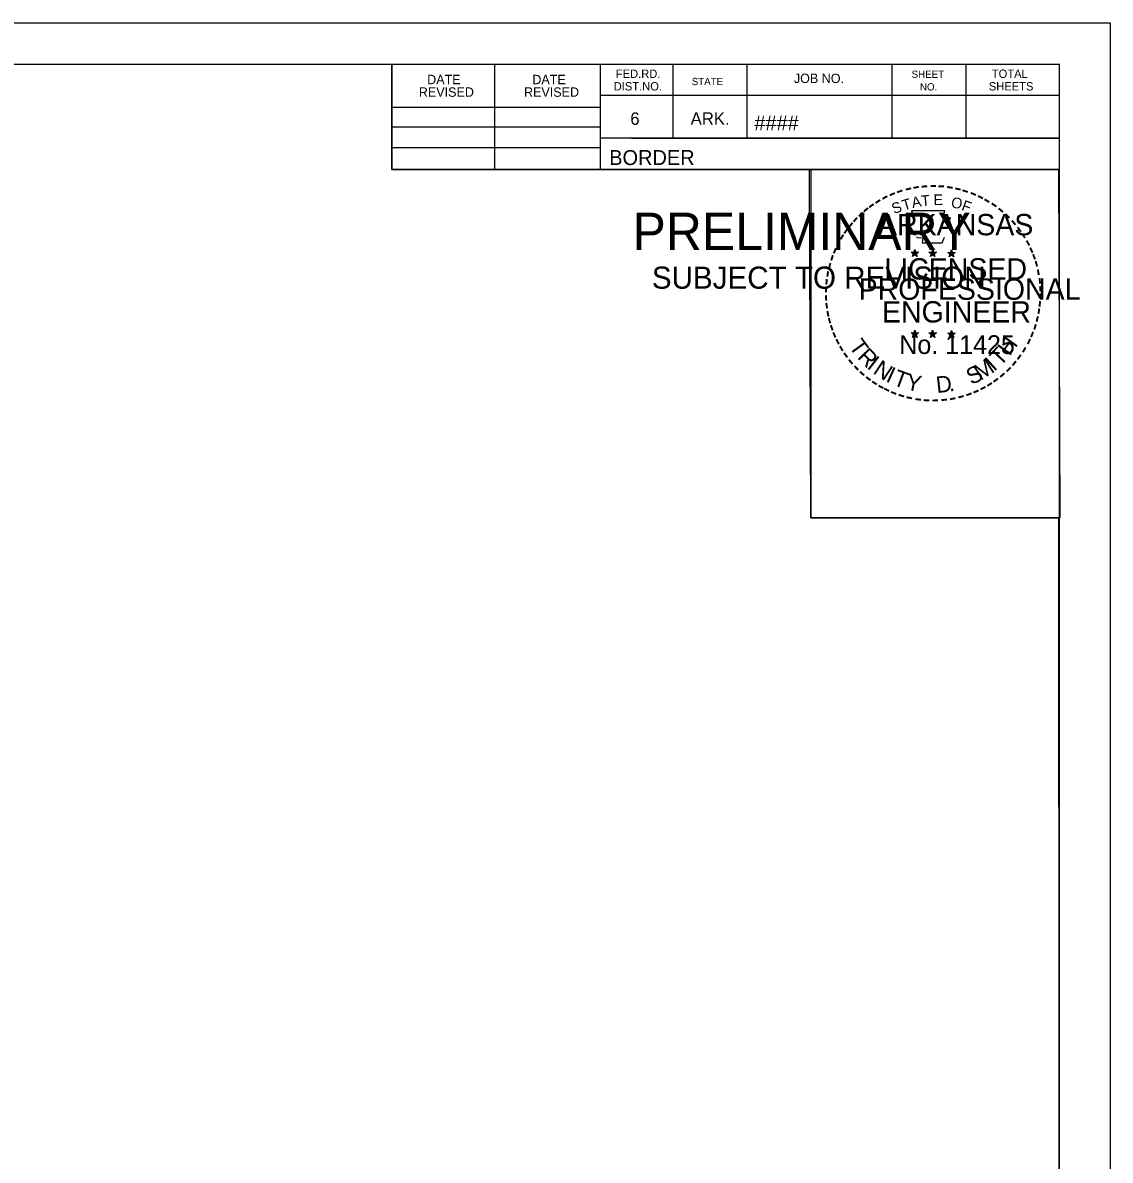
# Model space of a CAD drawing. Extents: x 961436 to 1372525, y 380079 to 2027791.
# Drawn here: x 1372422.8 to 1372524.7, y 380786.1 to 380892.8 of the extents above; entities that cross this region are included whole.
import ezdxf

# ---------------------------------------------------------------- set-up
doc = ezdxf.new("R2010")
doc.units = 0
for name, color, linetype in [('R_Border', 7, 'Continuous'), ('R_Border PE', 7, 'Continuous'), ('R_Border Prem', 7, 'Continuous'), ('R_No Plot', 7, 'Continuous')]:
    doc.layers.add(name, color=color, linetype=linetype)

msp = doc.modelspace()

# ---------------------------------------------------------------- linework, layer by layer
at = {"layer": 'R_Border'}
for p, q in [((1372203.81, 380888.88), (1372519.99, 380888.88)), ((1372457.35, 380879), (1372457.35, 380888.88)), ((1372467.03, 380879), (1372467.03, 380888.88)), ((1372476.89, 380888.88), (1372476.89, 380879)), ((1372483.73, 380888.88), (1372483.73, 380881.94)), ((1372490.67, 380888.88), (1372490.67, 380881.94)), ((1372504.25, 380888.88), (1372504.25, 380881.94)), ((1372511.19, 380888.88), (1372511.19, 380881.94)), ((1372519.99, 380683.42), (1372519.99, 380888.88)), ((1372519.99, 380885.94), (1372476.89, 380885.94)), ((1372519.99, 380885.96), (1372519.99, 380885.96)), ((1372457.35, 380884.86), (1372476.89, 380884.86)), ((1372457.35, 380883), (1372476.89, 380883)), ((1372519.99, 380881.94), (1372476.89, 380881.94)), ((1372479.85, 380881.94), (1372519.99, 380881.94)), ((1372457.35, 380881.06), (1372476.89, 380881.06)), ((1372519.99, 380879), (1372457.35, 380879))]:
    msp.add_line(p, q, dxfattribs=at)
at = {"layer": 'R_Border PE'}
for p, q in [((1372506.07, 380871.25), (1372506.42, 380871.14)), ((1372506.07, 380871.25), (1372506.32, 380871.21)), ((1372506.07, 380871.25), (1372506.31, 380871.13)), ((1372506.2, 380870.84), (1372506.42, 380871.14)), ((1372506.2, 380870.84), (1372506.33, 380871.09)), ((1372506.2, 380870.84), (1372506.42, 380871.06)), ((1372506.42, 380871.51), (1372506.38, 380871.25)), ((1372506.42, 380871.14), (1372506.42, 380871.51)), ((1372506.42, 380871.51), (1372506.47, 380871.26)), ((1372506.77, 380871.25), (1372506.42, 380871.14)), ((1372506.63, 380870.84), (1372506.42, 380871.14)), ((1372506.63, 380870.84), (1372506.42, 380871.06)), ((1372506.77, 380871.25), (1372506.48, 380871.2)), ((1372506.63, 380870.84), (1372506.5, 380871.13)), ((1372506.77, 380871.25), (1372506.56, 380871.15)), ((1372507.74, 380871.25), (1372508.09, 380871.14)), ((1372507.74, 380871.25), (1372507.99, 380871.21)), ((1372507.74, 380871.25), (1372507.98, 380871.13)), ((1372507.87, 380870.84), (1372508.09, 380871.14)), ((1372507.87, 380870.84), (1372508, 380871.09)), ((1372507.87, 380870.84), (1372508.09, 380871.06)), ((1372508.09, 380871.51), (1372508.05, 380871.25)), ((1372508.09, 380871.14), (1372508.09, 380871.51)), ((1372508.09, 380871.51), (1372508.14, 380871.26)), ((1372508.44, 380871.25), (1372508.09, 380871.14)), ((1372508.3, 380870.84), (1372508.09, 380871.14)), ((1372508.3, 380870.84), (1372508.09, 380871.06)), ((1372508.44, 380871.25), (1372508.15, 380871.2)), ((1372508.3, 380870.84), (1372508.17, 380871.13)), ((1372508.44, 380871.25), (1372508.23, 380871.15)), ((1372509.5, 380871.24), (1372509.85, 380871.13)), ((1372509.5, 380871.24), (1372509.76, 380871.19)), ((1372509.5, 380871.24), (1372509.74, 380871.12)), ((1372509.64, 380870.83), (1372509.85, 380871.13)), ((1372509.64, 380870.83), (1372509.76, 380871.08)), ((1372509.64, 380870.83), (1372509.85, 380871.05)), ((1372509.85, 380871.49), (1372509.81, 380871.24)), ((1372509.85, 380871.13), (1372509.85, 380871.49)), ((1372509.85, 380871.49), (1372509.9, 380871.24)), ((1372510.2, 380871.24), (1372509.85, 380871.13)), ((1372510.07, 380870.83), (1372509.85, 380871.13)), ((1372510.07, 380870.83), (1372509.85, 380871.05)), ((1372510.2, 380871.24), (1372509.91, 380871.19)), ((1372510.07, 380870.83), (1372509.93, 380871.12)), ((1372510.2, 380871.24), (1372510, 380871.14)), ((1372506.07, 380863.68), (1372506.42, 380863.57)), ((1372506.07, 380863.68), (1372506.32, 380863.63)), ((1372506.07, 380863.68), (1372506.3, 380863.56)), ((1372506.2, 380863.27), (1372506.42, 380863.57)), ((1372506.2, 380863.27), (1372506.33, 380863.51)), ((1372506.2, 380863.27), (1372506.41, 380863.49)), ((1372506.42, 380863.93), (1372506.37, 380863.68)), ((1372506.63, 380863.27), (1372506.41, 380863.48)), ((1372506.42, 380863.57), (1372506.42, 380863.93)), ((1372506.42, 380863.93), (1372506.46, 380863.68)), ((1372506.76, 380863.68), (1372506.42, 380863.57)), ((1372506.63, 380863.27), (1372506.42, 380863.57)), ((1372506.76, 380863.68), (1372506.48, 380863.63)), ((1372506.63, 380863.27), (1372506.49, 380863.56)), ((1372506.76, 380863.68), (1372506.56, 380863.58)), ((1372507.74, 380863.68), (1372508.08, 380863.57)), ((1372507.74, 380863.68), (1372507.99, 380863.63)), ((1372507.74, 380863.68), (1372507.97, 380863.56)), ((1372507.87, 380863.27), (1372508.08, 380863.57)), ((1372507.87, 380863.27), (1372507.99, 380863.51)), ((1372507.87, 380863.27), (1372508.08, 380863.49)), ((1372508.08, 380863.93), (1372508.04, 380863.68)), ((1372508.08, 380863.57), (1372508.08, 380863.93)), ((1372508.08, 380863.93), (1372508.13, 380863.68)), ((1372508.43, 380863.68), (1372508.08, 380863.57)), ((1372508.3, 380863.27), (1372508.08, 380863.57)), ((1372508.3, 380863.27), (1372508.08, 380863.48)), ((1372508.43, 380863.68), (1372508.15, 380863.63)), ((1372508.3, 380863.27), (1372508.16, 380863.56)), ((1372508.43, 380863.68), (1372508.23, 380863.58)), ((1372509.5, 380863.67), (1372509.85, 380863.56)), ((1372509.5, 380863.67), (1372509.76, 380863.62)), ((1372509.5, 380863.67), (1372509.74, 380863.55)), ((1372509.64, 380863.26), (1372509.85, 380863.56)), ((1372509.64, 380863.26), (1372509.76, 380863.5)), ((1372509.64, 380863.26), (1372509.85, 380863.48)), ((1372509.85, 380863.92), (1372509.81, 380863.67)), ((1372509.85, 380863.56), (1372509.85, 380863.92)), ((1372509.85, 380863.92), (1372509.9, 380863.67)), ((1372510.2, 380863.67), (1372509.85, 380863.56)), ((1372510.06, 380863.26), (1372509.85, 380863.56)), ((1372510.06, 380863.26), (1372509.85, 380863.47)), ((1372510.2, 380863.67), (1372509.91, 380863.62)), ((1372510.06, 380863.26), (1372509.93, 380863.55)), ((1372510.2, 380863.67), (1372509.99, 380863.57))]:
    msp.add_line(p, q, dxfattribs=at)
for points in [[(1372506.11, 380875.13), (1372506.38, 380874.3)], [(1372509.62, 380874.21), (1372509.76, 380874.49), (1372509.08, 380874.47), (1372509.23, 380875.13), (1372506.11, 380875.13)], [(1372506.6, 380872.71), (1372506.6, 380872.62), (1372507.17, 380872.6), (1372507.11, 380872.13), (1372508.98, 380872.13), (1372509.18, 380872.66)], [(1372506.42, 380871.51), (1372506.63, 380870.84), (1372506.07, 380871.25), (1372506.77, 380871.25), (1372506.2, 380870.84), (1372506.42, 380871.51)], [(1372508.09, 380871.51), (1372508.3, 380870.84), (1372507.74, 380871.25), (1372508.44, 380871.25), (1372507.87, 380870.84), (1372508.09, 380871.51)], [(1372509.85, 380871.49), (1372510.07, 380870.83), (1372509.5, 380871.24), (1372510.2, 380871.24), (1372509.64, 380870.83), (1372509.85, 380871.49)], [(1372506.42, 380863.93), (1372506.63, 380863.27), (1372506.07, 380863.68), (1372506.76, 380863.68), (1372506.2, 380863.27), (1372506.42, 380863.93)], [(1372508.08, 380863.93), (1372508.3, 380863.27), (1372507.74, 380863.68), (1372508.43, 380863.68), (1372507.87, 380863.27), (1372508.08, 380863.93)], [(1372509.85, 380863.92), (1372510.06, 380863.26), (1372509.5, 380863.67), (1372510.2, 380863.67), (1372509.64, 380863.26), (1372509.85, 380863.92)]]:
    msp.add_lwpolyline(points, dxfattribs=at)
for centre, radius in [((1372506.42, 380871.14), 0.172), ((1372506.42, 380871.14), 0.145), ((1372506.42, 380871.14), 0.116), ((1372506.42, 380871.14), 0.0991), ((1372506.42, 380871.14), 0.0747), ((1372506.42, 380871.14), 0.0495), ((1372506.42, 380871.14), 0.0296), ((1372508.09, 380871.14), 0.172), ((1372508.09, 380871.14), 0.145), ((1372508.09, 380871.14), 0.116), ((1372508.09, 380871.14), 0.0991), ((1372508.09, 380871.14), 0.0747), ((1372508.09, 380871.14), 0.0495), ((1372508.09, 380871.14), 0.0296), ((1372509.85, 380871.13), 0.172), ((1372509.85, 380871.13), 0.145), ((1372509.85, 380871.13), 0.116), ((1372509.85, 380871.13), 0.0991), ((1372509.85, 380871.13), 0.0747), ((1372509.85, 380871.13), 0.0495), ((1372509.85, 380871.13), 0.0296), ((1372506.41, 380863.57), 0.172), ((1372506.41, 380863.57), 0.145), ((1372506.41, 380863.57), 0.116), ((1372506.41, 380863.57), 0.0991), ((1372506.41, 380863.57), 0.0747), ((1372506.41, 380863.57), 0.0495), ((1372506.41, 380863.57), 0.0296), ((1372508.08, 380863.57), 0.172), ((1372508.08, 380863.57), 0.145), ((1372508.08, 380863.57), 0.116), ((1372508.08, 380863.57), 0.0991), ((1372508.08, 380863.57), 0.0747), ((1372508.08, 380863.57), 0.0495), ((1372508.08, 380863.57), 0.0296), ((1372509.85, 380863.56), 0.172), ((1372509.85, 380863.56), 0.145), ((1372509.85, 380863.56), 0.116), ((1372509.85, 380863.56), 0.0991), ((1372509.85, 380863.56), 0.0747), ((1372509.85, 380863.56), 0.0495), ((1372509.85, 380863.56), 0.0296)]:
    msp.add_circle(centre, radius, dxfattribs=at)
at = {"layer": 'R_No Plot'}
for p, q in [((1372191.41, 380892.77), (1372524.74, 380892.77)), ((1372496.02, 380856.54), (1372496.02, 380856.54))]:
    msp.add_line(p, q, dxfattribs=at)
for points in [[(1372191.4, 380892.77), (1372524.74, 380892.77), (1372524.74, 380679.43), (1372191.4, 380679.43)], [(1372437.73, 380888.88), (1372457.35, 380888.88), (1372457.35, 380879), (1372473.46, 380879), (1372496.66, 380879), (1372496.66, 380846.33), (1372519.87, 380846.33), (1372519.99, 380683.42), (1372203.81, 380683.42), (1372203.81, 380888.88)], [(1372496.52, 380879), (1372519.87, 380879), (1372520.01, 380846.33), (1372496.66, 380846.33)]]:
    msp.add_lwpolyline(points, close=True, dxfattribs=at)

# ---------------------------------------------------------------- texts
at = {"layer": 'R_Border'}
for s, height, p in [('DATE', 0.879, (1372460.68, 380887.01)), ('DATE', 0.879, (1372470.54, 380887.01)), ('FED.RD.', 0.782, (1372478.37, 380887.6)), ('JOB NO.', 0.879, (1372495.07, 380887.12)), ('SHEET', 0.684, (1372506.11, 380887.6)), ('TOTAL', 0.782, (1372513.63, 380887.6)), ('REVISED', 0.879, (1372459.9, 380885.83)), ('REVISED', 0.879, (1372469.76, 380885.83)), ('DIST.NO.', 0.782, (1372478.17, 380886.42)), ('STATE', 0.684, (1372485.49, 380886.92)), ('NO.', 0.684, (1372506.89, 380886.42)), ('SHEETS', 0.782, (1372513.35, 380886.42)), ('6', 1.17, (1372479.73, 380883.2)), ('ARK.', 1.172, (1372485.39, 380883.2)), ('####', 1.4, (1372491.36, 380882.68)), ('BORDER', 1.4, (1372477.75, 380879.43))]:
    msp.add_text(s, height=height, rotation=360, dxfattribs=at).set_placement(p)
at = {"layer": 'R_Border PE'}
for s, height, rotation, p in [('-', 1.6, 19.1761, (1372504.86, 380876.26)), ('-', 1.6, 13.6301, (1372505.61, 380876.5)), ('-', 1.6, 10.2193, (1372506.29, 380876.66)), ('-', 1.6, 5.8968, (1372507.02, 380876.77)), ('-', 1.6, 0.1862, (1372507.79, 380876.84)), ('-', 1.6, 357.743, (1372508.51, 380876.83)), ('-', 1.6, 352.1617, (1372509.26, 380876.77)), ('-', 1.6, 347.2049, (1372509.97, 380876.66)), ('-', 1.6, 342.3362, (1372510.61, 380876.5)), ('-', 1.6, 34.0636, (1372503, 380875.3)), ('-', 1.6, 28.7918, (1372503.59, 380875.67)), ('-', 1.6, 24.3072, (1372504.23, 380875.99)), ('S', 1, 21.594, (1372504.47, 380874.81)), ('T', 1, 16.4036, (1372505.38, 380875.14)), ('A', 1, 11.2132, (1372506.21, 380875.39)), ('T', 1, 6.0228, (1372507.06, 380875.56)), ('E', 1, 0.8323, (1372508.16, 380875.67)), ('O', 1, 350.4515, (1372509.76, 380875.46)), ('F', 1, 340.0707, (1372510.72, 380875.23)), ('-', 1.6, 337.8551, (1372511.34, 380876.28)), ('-', 1.6, 334.1211, (1372511.98, 380876.01)), ('-', 1.6, 329.6409, (1372512.55, 380875.73)), ('-', 1.6, 325.8627, (1372513.2, 380875.37)), ('-', 1.6, 42.9622, (1372501.51, 380874.11)), ('-', 1.6, 38.9507, (1372501.94, 380874.53)), ('-', 1.6, 36.2317, (1372502.42, 380874.91)), ('ARKANSAS', 2, 360, (1372502.96, 380872.84)), ('-', 1.6, 320.5297, (1372513.81, 380874.94)), ('-', 1.6, 315.5786, (1372514.41, 380874.45)), ('-', 1.6, 50.6142, (1372500.66, 380873.15)), ('-', 1.6, 48.423, (1372501.06, 380873.63)), ('-', 1.6, 309.8797, (1372514.98, 380873.9)), ('-', 1.6, 58.0706, (1372499.92, 380872.05)), ('-', 1.6, 54.2325, (1372500.24, 380872.58)), ('-', 1.6, 306.6522, (1372515.5, 380873.3)), ('-', 1.4, 303.6753, (1372515.99, 380872.73)), ('-', 1.6, 67.7743, (1372499.35, 380870.83)), ('-', 1.6, 62.8713, (1372499.61, 380871.44)), ('-', 1.6, 299.6684, (1372516.31, 380872.12)), ('-', 1.6, 294.6628, (1372516.63, 380871.51)), ('-', 1.6, 72.3945, (1372499.13, 380870.2)), ('LICENSED', 2, 360, (1372503.56, 380868.69)), ('DWB', 0.01, 360, (1372506.41, 380871.14)), ('DWB', 0.01, 360, (1372508.08, 380871.14)), ('DWB', 0.01, 360, (1372509.84, 380871.12)), ('-', 1.6, 290.5728, (1372516.89, 380870.94)), ('-', 1.6, 81.2013, (1372498.8, 380868.77)), ('-', 1.6, 75.461, (1372498.93, 380869.48)), ('-', 1.6, 285.1233, (1372517.12, 380870.36)), ('-', 1.6, 280.5493, (1372517.32, 380869.61)), ('-', 1.6, 85.1863, (1372498.72, 380868.08)), ('PROFESSIONAL', 2, 360, (1372501.14, 380866.79)), ('-', 1.6, 276.5962, (1372517.48, 380868.85)), ('-', 1.6, 89.0622, (1372498.7, 380867.38)), ('-', 1.6, 274.3301, (1372517.54, 380868.12)), ('-', 1.6, 269.9407, (1372517.58, 380867.49)), ('-', 1.6, 94.1959, (1372498.73, 380866.65)), ('-', 1.6, 98.9479, (1372498.81, 380865.99)), ('ENGINEER', 2, 360, (1372503.33, 380864.66)), ('-', 1.6, 263.5172, (1372517.56, 380866.83)), ('-', 1.6, 101.7149, (1372498.94, 380865.25)), ('-', 1.6, 255.7626, (1372517.38, 380865.49)), ('-', 1.6, 260.9953, (1372517.49, 380866.17)), ('-', 1.6, 105.4578, (1372499.1, 380864.66)), ('-', 1.6, 109.0874, (1372499.32, 380864.03)), ('-', 1.6, 252.8681, (1372517.2, 380864.77)), ('-', 1.6, 114.0643, (1372499.57, 380863.43)), ('-', 1.6, 115.7289, (1372499.88, 380862.81)), ('T', 1.54, 306.0406, (1372500.18, 380862.41)), ('No. 11425', 1.757, 360, (1372504.95, 380861.71)), ('DWB', 0.01, 360, (1372506.4, 380863.56)), ('DWB', 0.01, 360, (1372508.07, 380863.56)), ('DWB', 0.01, 360, (1372509.84, 380863.55)), ('H', 1.54, 54.6088, (1372515.3, 380861.44)), ('-', 1.6, 244.6197, (1372516.71, 380863.47)), ('-', 1.6, 247.8887, (1372516.97, 380864.1)), ('-', 1.6, 120.4471, (1372500.23, 380862.23)), ('R', 1.54, 314.005, (1372500.94, 380861.36)), ('T', 1.54, 46.6444, (1372514.41, 380860.5)), ('-', 1.6, 239.0712, (1372516.32, 380862.72)), ('-', 1.6, 125.8934, (1372500.64, 380861.67)), ('-', 1.6, 130.7181, (1372501.1, 380861.11)), ('I', 1.54, 321.9694, (1372501.84, 380860.43)), ('N', 1.54, 326.5002, (1372502.41, 380859.95)), ('M', 1.54, 32.6563, (1372512.56, 380859.17)), ('I', 1.54, 42.1136, (1372513.84, 380860.02)), ('-', 1.6, 231.2538, (1372515.48, 380861.5)), ('-', 1.6, 233.8452, (1372515.91, 380862.07)), ('-', 1.6, 134.2238, (1372501.62, 380860.57)), ('-', 1.6, 138.9338, (1372502.14, 380860.11)), ('I', 1.54, 335.3603, (1372503.61, 380859.17)), ('T', 1.54, 339.8912, (1372504.27, 380858.84)), ('Y', 1.54, 347.8556, (1372505.49, 380858.4)), ('S', 1.54, 26.9312, (1372511.72, 380858.77)), ('-', 1.6, 221.0851, (1372514.48, 380860.43)), ('-', 1.6, 225.7653, (1372515.01, 380860.94)), ('-', 1.6, 144.6463, (1372502.7, 380859.7)), ('-', 1.6, 148.0898, (1372503.26, 380859.33)), ('-', 1.6, 151.5704, (1372503.84, 380859)), ('D', 1.54, 6.3969, (1372508.48, 380858.04)), ('-', 1.6, 212.2491, (1372513.4, 380859.57)), ('-', 1.6, 215.7363, (1372513.93, 380859.96)), ('-', 1.6, 154.6002, (1372504.36, 380858.76)), ('-', 1.6, 158.5612, (1372504.98, 380858.5)), ('-', 1.6, 162.7983, (1372505.67, 380858.29)), ('.', 1.54, 13.7642, (1372509.67, 380858.16)), ('-', 1.6, 195.4743, (1372510.92, 380858.39)), ('-', 1.6, 200.7184, (1372511.6, 380858.63)), ('-', 1.6, 204.2516, (1372512.22, 380858.9)), ('-', 1.6, 207.3568, (1372512.84, 380859.22)), ('-', 1.6, 167.5555, (1372506.38, 380858.13)), ('-', 1.6, 173.1155, (1372507.16, 380858.02)), ('-', 1.6, 176.5183, (1372507.9, 380857.96)), ('-', 1.6, 181.5918, (1372508.65, 380857.98)), ('-', 1.6, 185.8167, (1372509.46, 380858.06)), ('-', 1.6, 191.2858, (1372510.19, 380858.19))]:
    msp.add_text(s, height=height, rotation=rotation, dxfattribs=at).set_placement(p)
at = {"layer": 'R_Border Prem'}
for s, height, p in [('PRELIMINARY', 3.5, (1372479.94, 380871.46)), ('DWB', 0.01, (1372480.68, 380873.31)), ('SUBJECT TO REVISION', 2.0751, (1372481.75, 380867.83))]:
    msp.add_text(s, height=height, rotation=360, dxfattribs=at).set_placement(p)

doc.saveas('drawing.dxf')
